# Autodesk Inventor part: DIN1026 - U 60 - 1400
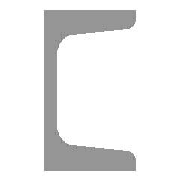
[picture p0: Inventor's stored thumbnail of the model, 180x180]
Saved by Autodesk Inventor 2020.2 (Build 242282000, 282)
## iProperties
Manager: www.cadconsulting.pl
Company: Fabian Stasiak CAD Consulting
Created: 2014-02
Part Number: DIN1026 - U 60 - 1400
Material: Stal, miękka
Description: Ceownik
Document SubType Name: Modeling
Standard: DIN 1026
Designer: F.Stasiak
Standard Revision: 2000
Standards Organization: DIN
Language: pl-PL
Size Designation: U 60 - 1400
Categories: <MemberInstance><Categories><Category DisplayName="Kształtowniki konstrukcyjne" InternalName="089c4875-fa83-4c05-b084-43b9cc11f5ed" Mnemonic="GRDR"><CategoryPar
Stock Number: U 60
Density: 7.85 g/cm^3
Appearance: Częściowo polerowana
Catalog Web Link: www.expertbooks.pl
IsCustomPart: 1
G_L: 1400,000 mm
Author: F.Stasiak
Subject: Zbiór ćwiczeń. Autodesk Inventor 2020. Kurs Professional
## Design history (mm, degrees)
node "Płaszczyzna początkowa"
node "Płaszczyzna końcowa"
sketch "Szkic"
  geometry: L1 (0, 0)-(0, 30); L2 (0, 30)-(30, 30); L3 (30, 30)-(30, 27.97); L4 (27.239, 24.979)-(11.522, 23.722); L5 (6, 17.741)-(6, 0); L6 (6, 0)-(0, 0); L7 (15, 30)-(15, 24); L8 (30, 25.2)-(30, 24); L9 (30, 24)-(15, 24); L10 (0, 15)-(0, -27); L11 (-5.539, 0)-(16.007, 0); L12 (0, 0)-(0, -30); L13 (0, -30)-(30, -30); L14 (30, -30)-(30, -27.97); L15 (27.239, -24.979)-(11.522, -23.722); L16 (6, -17.741)-(6, 0); L17 (0, 23.4)-(0, -35.4) reference; L18 (-9.848, 0)-(20.316, 0) reference; A1 r 6 centre (12, 17.741) between (11.522, 23.722) and (6, 17.741); A2 r 6 centre (12, -17.741) between (6, -17.741) and (11.522, -23.722); A3 r 3 centre (27, 27.97) between (27.239, 24.979) and (30, 27.97); A4 r 3 centre (27, -27.97) between (30, -27.97) and (27.239, -24.979); 5 further points
  constraints: 32 end point, 10 point on line, 8 point on circle, 8 tangent, 6 symmetric about line, 4 centre point, 4 parallel, 3 collinear, 3 perpendicular, 2 equal radius, 2 midpoint, 5 other
  dimensions: "d0" = 6 distance between parallel lines of L1 L5 (= G_T); "d1" = 30 distance between parallel lines of L6 L2 (= 0.5 x G_H); "d2" = 30 distance between parallel lines of L3 L1 (= G_W); "d3" = 6 distance of L2.end L8.end (= G_T1); "d4" = 15 distance of L7.start L2.end (= G_C); "d5" = 1.2 distance of L8.start L8.end (computed from G_NG, G_C); "d23" = 6 radius of A1 (= G_IR); "d24" = 3 radius of A3 (= G_ER); "d25" = 0 distance between parallel lines of L10 L12 (computed from ex)
extrude "Bryła" new body sketch "Szkic" stored distance "d6" = 1400 (= G_L); taper "d7" = 0 deg
node "Driven Length"
  sketch "Sketch3"
    geometry: L1 (0, 0)-(10, 0) reference
    constraints: 2 end point, 1 horizontal
  workplane "Work Plane3"
  sketch "Sketch4"
    geometry: L1 (-2, 0)-(12, 0) reference; L2 (-2, 1400)-(12, 1400) reference
    dimensions: "d29" = 1400 distance between parallel lines of L1 L2 (derived)
body "Solid1"
other parameters: "G_W" = 30 [user parameter; used in 1 equation term], "G_T" = 6 [user parameter; used in 1 equation term], "G_T1" = 6 [user parameter; used in 1 equation term], "G_NG" = 0.8 [user parameter; used in 1 equation term], "G_ER" = 3 [user parameter; used in 1 equation term], "G_IR" = 6 [user parameter; used in 1 equation term], "G_C" = 15 [user parameter; used in 2 equation terms], "G_L" = 1400 (= d29) [user parameter; used in 1 equation term], "ex" = 0 [user parameter; used in 1 equation term], "G_OFFSET_START" = 0 [user parameter; used in 1 equation term], "G_OFFSET_END" = 0 [user parameter; used in 1 equation term], "d26" = 0 (computed from G_OFFSET_START), "d28" = 90 deg
